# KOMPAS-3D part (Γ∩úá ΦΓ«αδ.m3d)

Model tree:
1. Эскиз:1
2. Операция выдавливания:1
     Расстояние 1 = 22; Расстояние 2 = 3
3. Эскиз:2
4. Операция выдавливания:2
     Расстояние 1 = 2; Расстояние 2 = 3
5. Эскиз:3
6. Операция выдавливания:3
     Расстояние 1 = 5; Расстояние 2 = 3
7. Эскиз:4
8. Операция выдавливания:4
     Расстояние 1 = 0.1; Расстояние 2 = 3
9. Эскиз:5
10. Операция выдавливания:5
     Расстояние 1 = 1.5; Расстояние 2 = 0.5
11. Эскиз:6
12. Операция выдавливания:6
     Расстояние 1 = 2; Расстояние 2 = 0.5
13. Ломаная:2
14. Перпендикулярная плоскость:2
15. Эскиз:13
16. Кинематическая операция:2
     Толщина стенки 1 = 1; Толщина стенки 2 = 1
17. Смещенная плоскость:1
     Расстояние = 2
18. Эскиз:14
19. Операция выдавливания:12
     Расстояние 1 = 2; Расстояние 2 = 0.5
20. Эскиз:15
21. Операция выдавливания:13
     Расстояние 1 = 3; Расстояние 2 = 0.5
22. Эскиз:16
23. Операция выдавливания:14
     Расстояние 1 = 2; Расстояние 2 = 0.5

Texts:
  stalker61
  Сплав АЛ8  ГОСТ 1583-93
